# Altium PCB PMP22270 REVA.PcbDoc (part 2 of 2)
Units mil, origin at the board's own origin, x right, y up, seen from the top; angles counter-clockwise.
Board outline 4330.71 x 3937.01 mil, 4 copper layers (Top Layer, Signal Layer 1, Signal Layer 2, Bottom Layer), stack 41.2 mil thick; 92 components, 40 nets, 216 pads, 127 vias.
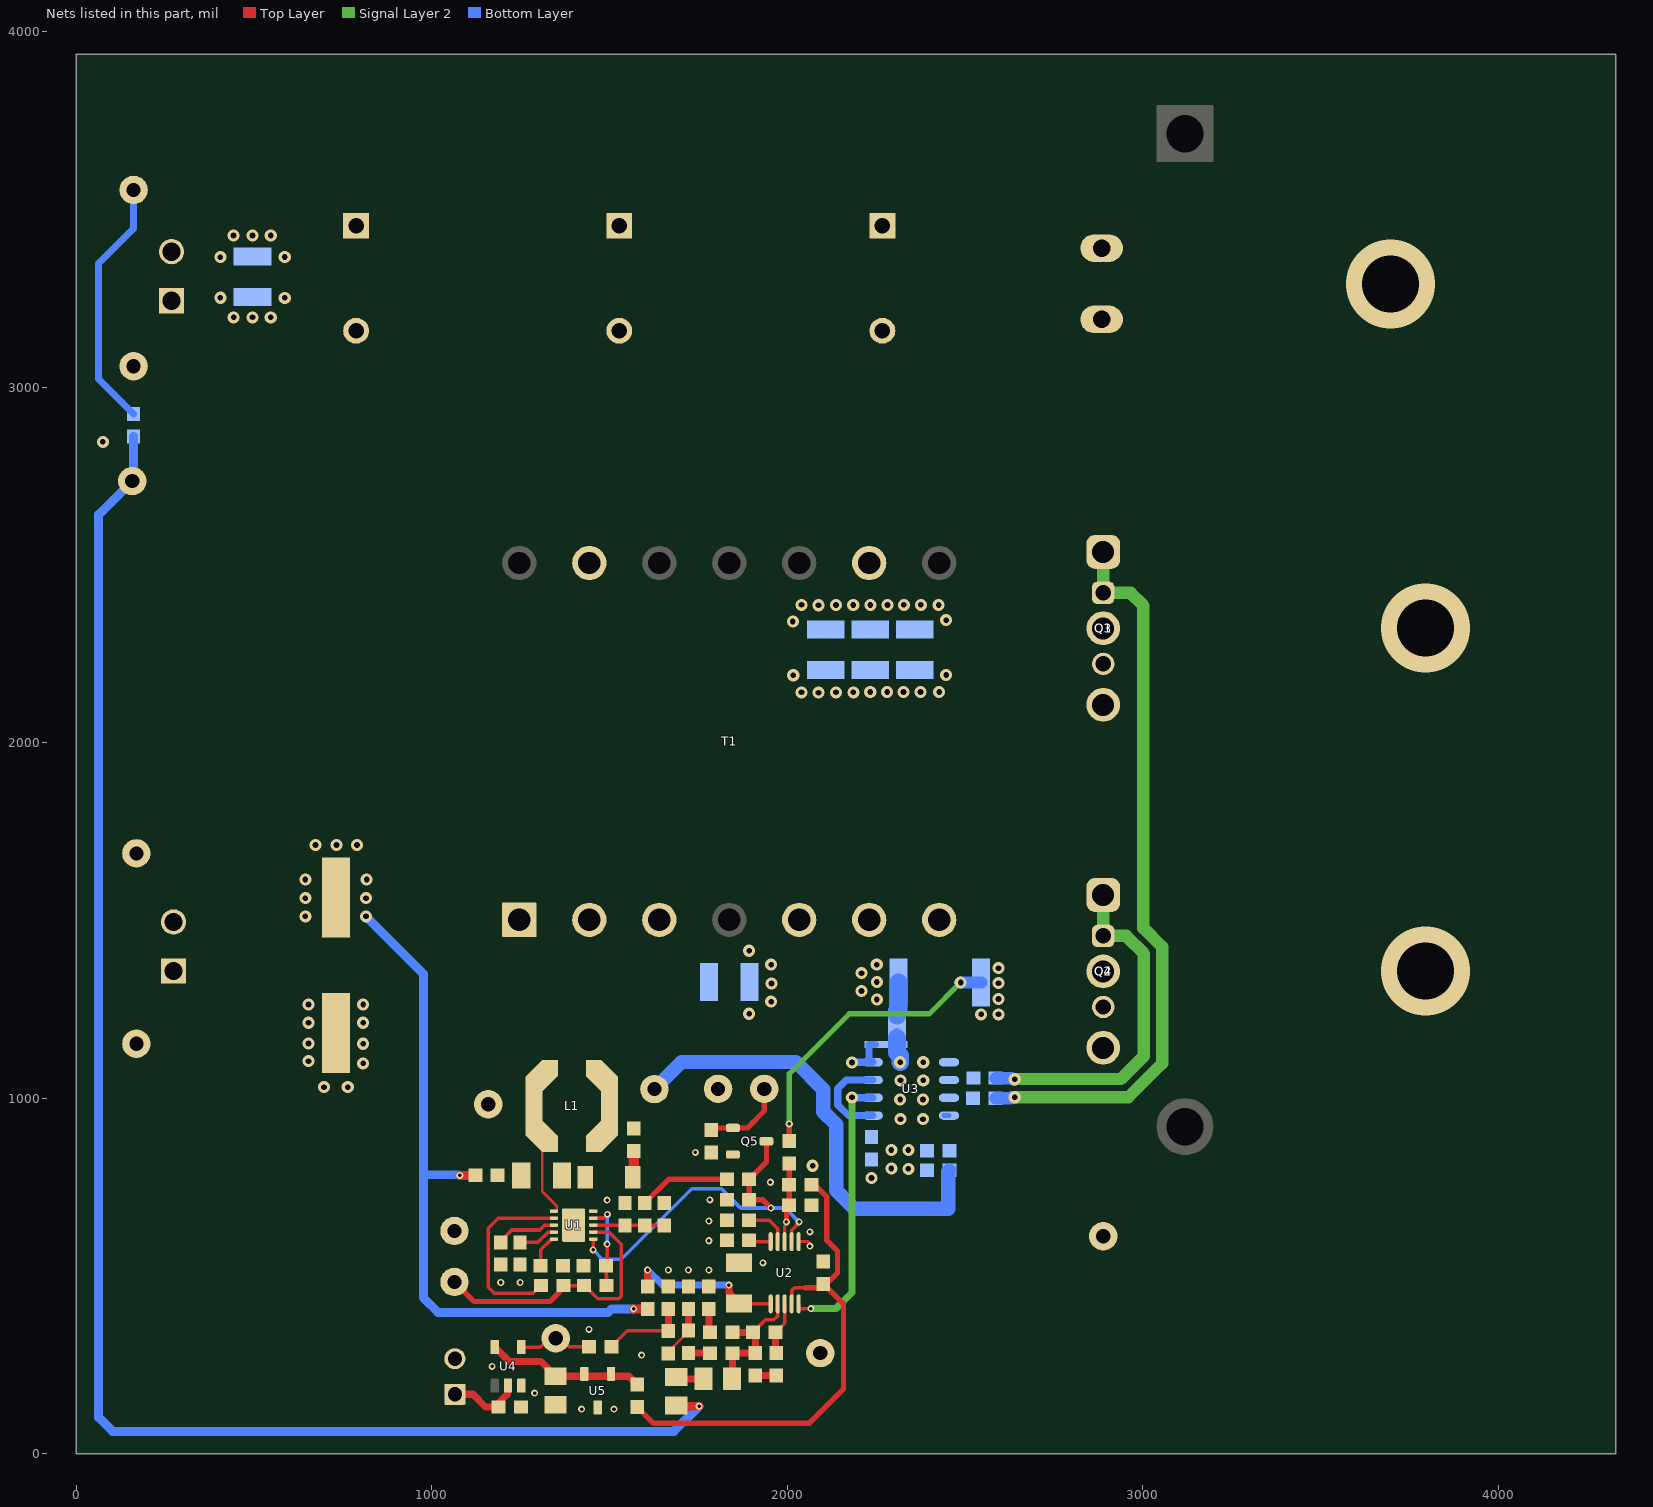
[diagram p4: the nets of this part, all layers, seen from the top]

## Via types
v1: diameter 34, hole 16, Top Layer to Bottom Layer, 86 vias
v2: diameter 20, hole 10, Top Layer to Bottom Layer, 33 vias
v3: diameter 19.68, hole 7.87, Top Layer to Bottom Layer, 4 vias
v4: diameter 250, hole 160, Top Layer to Bottom Layer, 3 vias
v5: diameter 160.24, hole 105.12, Top Layer to Bottom Layer, 1 vias

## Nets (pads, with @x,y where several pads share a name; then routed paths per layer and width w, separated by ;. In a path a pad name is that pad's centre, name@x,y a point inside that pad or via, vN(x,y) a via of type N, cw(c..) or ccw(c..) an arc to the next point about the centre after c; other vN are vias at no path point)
10V: C13.1 C15.1 C18.1 C25.1 L1.2 R3.2 R4.2 R13.2 TP4.1 U3.1 U3.3 U3.8 | length 1827
  Top Layer w10: C25.1@1654.09,704.92 C25.1@1654.09,705.9 ; R13.2@1827.2,769.31 R13.2@1830.06,772.17
  Top Layer w15: R3.2@1599.09,704.92 1666.34,772.17 R13.2@1830.06,772.17
  Bottom Layer w15: U3.8@2440.96,951.47 U3.8@2455.06,951.47
  Bottom Layer w20: U3.1@2240.49,951.47 2172.3,951.47 2142.22,981.56 2142.22,1027.79 2165.91,1051.47 U3.3@2240.49,1051.47
  Bottom Layer w40: TP4.1@1626.53,1025.87 1703.02,1102.36 2024.31,1102.36 2101.56,1025.11 2101.56,962.32 2137.8,926.08 2137.8,740.89 2189.59,689.09 2452.87,689.09 2452.87,794.23 C18.1@2455.96,797.32
Drain: C3.2 C4.2 C6.2 Q1.2 Q2.2 Q3.2 Q4.2 T1.5 T1.6 T1.7 TP7.1
  other v1: 2088,2141 2040,2141.89 2137,2141.89 2186,2142 2233.52,2143 2281,2143 2327,2143 2375,2143 2427.53,2143 2017,2190 2447,2191
  other v4: 3795.28,1358.44 3795.28,2322.83
Gate1: Q1.1 Q3.1 R11.2 | length 2061.8
  Signal Layer 2 w35: v1(2640,1003.12) 2640.12,1003 2959.3,1003 3055,1098.7 3055,1426 3002,1479 3002,2386 2966,2422 Q1.1@2888.83,2422 Q3.1@2888.83,2537
  Bottom Layer w35: R11.2@2586.27,1000.52 2629.52,1000.52 2632.12,1003.12 v1(2640,1003.12)
Gate2: Q2.1 Q4.1 R15.2 | length 983.4
  Signal Layer 2 w35: v1(2640,1053.61) 2640.73,1054.34 2938.81,1054.34 3003,1118.53 3003,1407.3 2953.3,1457 Q2.1@2888.83,1457 Q4.1@2888.83,1572
  Bottom Layer w35: R15.2@2586.5,1057.06 2630.94,1057.06 2634.39,1053.61 v1(2640,1053.61)
GND: C1.2 C2.2 C5.2 C7.2 C8.2 C9.2 C10.2 C11.2 C12.2 C13.2 C14.2 C16.2 C17.2 C21.2 C22.2 C23.2 C24.2 J1.1 J2.1 J3.2 NT1.1 NT2.1 Q5.2 R6.1 R7.1 R8.1 R9.1 R19.1 R21.1 R23.1 R24.1 R25.1 R31.1 T1.13 TP2.1 TP8.1 TP11.1 TP12.1 TP16.1 U1.10 U1.11 U2.6 U3.4 U4.3 U5.3 | length 287.4
  Top Layer w8: U1.10@1447.26,682.79 U1.10@1454.2,682.79 ; U2.6@2032.15,596.91 2058.94,596.91 2063.64,592.21 v2(2063.64,584.31)
  Bottom Layer w20: v1(2182.22,1100.79) 2182.91,1101.47 U3.4@2240.49,1101.47 2229.58,1112.38 2229.58,1151.47 NT2.1@2247.77,1151.47 ; NT1.1@2308.55,1219.79 NT1.1@2308.55,1232.28
  Bottom Layer w50: NT1.1@2308.55,1232.28 2308.55,1246.54 2313.08,1251.07 R25.1@2313.08,1325.79
  other v1: 2237.22,775.79 2071.64,810.42 696.85,1031.5 763.78,1031.5 807.09,1098.43 653.54,1104.64 653.54,1153.97 807.09,1153.54 653.54,1212.6 807.09,1212.6 1892.78,1238 653.54,1263.78 807.09,1263.78 1954.78,1272 2252,1278 2209,1302 1955.78,1323 2252,1327 2209,1352 1954.78,1376 2251.78,1376 1892.78,1415 74.8,2846.46 442.91,3196.85 496.06,3196.85 547.24,3196.85 405.51,3251.97 586.61,3251.53
  other v2: 1421.72,125.77 1512.7,125.77 1289.4,170.77 1169.88,246.08 1590.55,277.85 1442.46,350.22 1194.09,482.01 1248.49,482.01 1665.59,517.03 1722.07,517.03 1779.63,517.03 1931.56,537.33 1779.63,599.31 2063.64,624.31 1779.63,654.94 1493.53,713.46 1782.58,714.31 1952.76,763.87 1741.56,847.82
NetC1_1: C1.1 C2.1 J1.2 R1.2 R12.2 T1.1 T1.2 T1.3 TP1.1 | length 1939.3
  Top Layer w25: v2(1078.74,783.46) 1122.55,783.46 R1.2@1122.59,783.42 ; v2(1567.98,407.6) R12.2@1608.09,407.6
  Bottom Layer w25: v1(814.96,1511.81) 976.38,1350.39 976.38,785.1 ; v2(1078.74,783.46) 1077.1,785.1 976.38,785.1 ; v2(1567.98,407.6) 1506.55,407.6 1496.59,397.64 1018.14,397.64 976.38,439.4 976.38,785.1
  other v1: 644.47,1511.81 644.47,1562.99 814.96,1562.99 644.47,1615.54 817.09,1615.54 673.23,1712.6 732.28,1712.6 789.97,1712.6
NetC3_1: C3.1 C4.1 C6.1 D1.2 T1.9
  other v1: 2016,2341 2447,2345 2088,2387 2040,2388 2137,2387.89 2185.76,2387.89 2233.8,2387.89 2282,2387.89 2328,2388 2376,2388 2426,2387.89
NetC5_1: C5.1 R1.1 R2.2 U1.2 | length 527.8
  Top Layer w10: R2.2@1307.59,473.42 1306.61,473.42 1284.37,451.19 1284.09,451.47 1176.04,451.47 1159.09,468.42 1159.09,634.72 1187.47,663.11 U1.2@1343.97,663.11
NetC7_1: C7.1 U1.4 | length 107.4
  Top Layer w10: C7.1@1248.49,594.92 1298.34,594.92 1327.16,623.74 U1.4@1343.97,623.74
NetC8_1: C8.1 R4.1 | length 74.3
  Top Layer w30: C8.1@1566.01,778.42 1567.98,780.39 R4.1@1567.98,851.93
NetC9_1: C9.1 C10.1 C11.1 C12.1 D1.1 J2.2 R10.1 TP6.1 | length 711.5
  Top Layer w20: TP6.1@161.42,3555.12 TP6.1@161.42,3555.12
  Bottom Layer w20: R10.1@161.42,2925.2 62.99,3023.62 62.99,3348.06 161.42,3446.49 TP6.1@161.42,3555.12
  other v1: 405.51,3366.14 586.61,3366.72 442.54,3426.8 496.06,3426.8 547.24,3426.8
  other v4: 3697,3291
NetC14_1: C14.1 R12.1 U2.1 | length 445.3
  Top Layer w10: C14.1@1864.08,423.16 1865.51,421.72 U2.1@1953.41,421.72
  Top Layer w20: v2(1607.43,517.03) 1607.43,471.25 R12.1@1608.09,470.59 ; v2(1835.73,474.71) 1835.73,453.06 C14.1@1864.08,423.16
  Bottom Layer w20: v2(1607.43,517.03) 1649.75,474.71 v2(1835.73,474.71)
NetC15_2: C15.2 C18.2 NT1.2 NT2.2 U3.5 | length 92.1
  Bottom Layer w15: 2308.55,1169.79 NT1.2@2308.55,1189.79
  Bottom Layer w50: 2308.55,1169.79 2308.55,1128.69 2317.77,1119.47 v1(2317.77,1101.47)
  other v1: 2340.61,801.47 2292.77,802.36 2292.77,854.91 2340.61,854.91 2318.8,941.47 2381.75,941.47 2317.77,996.47 2381.75,996.47 2318.8,1050.53 2382.77,1050.53 2382.77,1101.47
NetC16_1: C16.1 U2.10 | length 62
  Top Layer w10: C16.1@1893.05,600.97 1897.11,596.91 U2.10@1953.41,596.91
NetC19_1: C19.1 R17.2 U2.3 | length 150
  Top Layer w10: C19.1@1967.07,341.72 1992.78,367.43 U2.3@1992.78,421.72
  Top Layer w20: C19.1@1967.07,341.72 1967.07,285.22 R17.2@1969.08,283.21
NetC19_2: C19.2 C20.2 R16.1 R20.2 R30.1 U2.2 | length 373.5
  Top Layer w10: C19.2@1904.08,341.72 1939.08,376.72 1962.05,376.72 1973.09,387.76 U2.2@1973.09,421.72
  Top Layer w20: R16.1@1844.74,210.77 1845.57,211.6 R30.1@1845.57,283.21 ; R20.2@1845.57,341.72 C19.2@1904.08,341.72 1908.92,341.72 1910.34,340.3 C20.2@1910.34,283.21 R30.1@1854.08,283.21
NetC20_1: C20.1 R17.1 | length 58.7
  Top Layer w20: C20.1@1910.34,220.22 R17.1@1969.08,220.22
NetC21_1: C21.1 R18.1 R22.1 U2.8 | length 224.8
  Top Layer w8: U2.8@1992.78,596.91 1992.78,640.3 1997.83,645.36 v2(1997.83,652.23)
  Top Layer w10: C21.1@1997.83,691.45 C21.1@2005.69,699.31
  Top Layer w15: v2(1997.83,652.23) C21.1@1997.83,691.45 ; C21.1@2005.69,699.31 R18.1@2005.69,756.56 R22.1@2005.69,816.32
NetC22_1: C22.1 R26.2 U4.5 U5.1 U5.2 | length 444.4
  Top Layer w20: U4.5@1177.28,300.22 1218.2,259.29 1307.12,259.29 C22.1@1348.09,218.33 1554.67,218.33 R26.2@1578.09,194.9
NetC23_1: C23.1 R27.1 R28.2 | length 240.5
  Top Layer w10: R27.1@1505.45,301.08 1550.14,345.77 R28.2@1665.59,345.77
  Top Layer w20: R28.2@1665.59,345.77 C23.1@1665.59,407.6
NetC24_1: C24.1 R28.1 R29.1 | length 148.2
  Top Layer w8: R28.1@1665.59,282.78 1665.59,287.59 1722.07,344.06 R29.1@1722.07,347.26
  Top Layer w20: R29.1@1722.07,347.26 C24.1@1722.07,407.6
NetC25_2: C25.2 R3.1 R8.2 U1.8 | length 202.1
  Top Layer w10: U1.8@1454.2,643.42 1654.6,643.42 1654.09,642.91 C25.2@1654.09,641.93
NetJ3_1: J3.1 R31.2 U4.2 | length 209.6
  Top Layer w20: J3.1@1065.16,167.54 1116.04,167.54 1151.63,131.95 R31.2@1188.18,131.95 1188.18,143.13 1213,167.95 ; 1213,167.1 1213,167.95 ; U4.2@1214.68,191.95 1213,190.27 1213,167.95
NetL1_1: L1.1 TP3.1 U1.1 | length 236
  Top Layer w8: L1.1@1310.48,893.75 1311,893.23 1311,738.18 1351.89,697.3 1351.89,682.79 U1.1@1343.97,682.79
NetQ5_1: Q5.1 R23.2 TP10.1 | length 233.5
  Top Layer w15: R23.2@1786.56,910.81 1792.46,916.72 Q5.1@1847.07,916.72 1888.09,916.72 1935.51,964.14 TP10.1@1935.51,1026.6
NetR2_1: R2.1 R5.2 TP5.1 U1.7 | length 771.7
  Top Layer w10: R2.1@1370.58,473.42 R5.2@1428.61,473.42 1429.6,473.42 1466.95,436.07 1525.28,436.07 1532.87,443.66 1532.87,589.64 1498.77,623.74 U1.7@1454.2,623.74
  Top Layer w15: TP5.1@1064.09,483.46 1119.09,428.46 1332.66,428.46 1360.72,456.51 1360.72,463.56 R2.1@1370.58,473.42
NetR5_1: R5.1 R6.2 U1.9 | length 245.6
  Top Layer w10: U1.9@1454.2,663.11 1471.01,663.11 1471.33,663.42 1484.09,663.42 v2(1494.09,673.42) ; R5.1@1491.61,473.42 R6.2@1490.58,528.98 1493.53,531.93 v2(1493.53,589.88)
  Bottom Layer w10: v2(1493.53,589.88) 1494.09,590.43 v2(1494.09,673.42)
NetR7_2: R7.2 U1.3 | length 172.1
  Top Layer w10: R7.2@1194.09,594.92 1194.09,598.58 1225.11,629.61 1303.61,629.61 1317.43,643.42 U1.3@1343.97,643.42
NetR9_2: R9.2 U1.5 | length 94.7
  Top Layer w10: R9.2@1306.57,528.98 1306.57,573.74 1336.88,604.05 U1.5@1343.97,604.05
NetR10_2: R10.2 R14.2 TP9.1 | length 4599.9
  Top Layer w25: R14.2@1688.09,135.77 1690,133.86 v2(1751.97,133.86)
  Bottom Layer w25: R10.2@161.42,2862.2 161.42,2740.16 TP9.1@157.48,2736.22 62.99,2641.73 62.99,102.36 102.36,62.99 1681.1,62.99 v2(1751.97,133.86)
NetR11_1: R11.1 R15.1 U3.6 U3.7
NetR14_1: R14.1 R16.2 | length 78.7
  Top Layer w20: R14.1@1688.09,215.77 1693.09,210.77 R16.2@1764.74,210.77
NetR19_2: R19.2 U2.9 | length 126.1
  Top Layer w10: R19.2@1893.05,656.83 1949.47,656.83 1973.09,633.21 U2.9@1973.09,596.91
NetR20_1: R20.1 R24.2 | length 67.1
  Top Layer w15: R20.1@1779.63,344.67 R20.1@1782.58,341.72
  Top Layer w20: R20.1@1779.63,344.67 R24.2@1779.63,407.6
NetR27_2: R27.2 TP14.1 U4.4 | length 210.7
  Top Layer w10: U4.4@1252.08,300.22 1305.1,300.22 1330.03,325.14 TP14.1@1348.96,325.14 1363.17,325.14 1387.22,301.08 R27.2@1442.46,301.08
NetR29_2: R29.2 R30.2 | length 61
  Top Layer w20: R29.2@1722.07,284.27 1723.13,283.21 R30.2@1782.58,283.21
NetU2_5: U2.5 U3.2 | length 801.8
  Top Layer w10: U2.5@2032.15,421.72 2032.15,406.47 2033.95,408.28 v2(2066.56,408.28)
  Signal Layer 2 w20: v2(2066.56,408.28) 2136.7,408.28 2182.22,453.8 v1(2182.22,1002.79)
  Bottom Layer w20: v1@2173.73,1001.47 2175.04,1002.79 v1(2182.22,1002.79) 2183.54,1001.47 U3.2@2240.49,1001.47
PG: Q5.3 R13.1 R21.2 U1.6 U2.7 | length 1060.5
  Top Layer w10: v2(1454.09,573.74) 1454.2,573.86 U1.6@1454.2,604.05 ; U2.7@2012.46,596.91 2012.46,629.31 2033.29,650.15 v2(2033.29,652.23)
  Top Layer w15: Q5.3@1941.56,879.31 1941.56,820.68 R13.1@1893.05,772.17 R21.2@1893.05,714.31 1931.41,714.31 v2(1954.27,691.45)
  Bottom Layer w10: v2(1454.09,573.74) 1480.15,547.68 1533.6,547.68 1731.19,745.26 1814.96,745.26 1868.77,691.45 v2(1954.27,691.45) 1994.07,691.45 v2(2033.29,652.23)
Source: Q1.3 Q2.3 Q3.3 Q4.3 R22.2 R25.2 | length 835.6
  Top Layer w15: R22.2@2005.69,879.31 v2(2005.69,928.05)
  Signal Layer 2 w15: v2(2005.69,928.05) 2005.69,1068.86 2174.83,1238 2400.01,1238 v1(2487.8,1325.79)
  Bottom Layer w35: v1(2487.8,1325.79) R25.2@2545.36,1325.79
  other v1: 2545.36,1236.22 2594.49,1236.22 2594.49,1279.53 2594.49,1324 2594.49,1366.14
VCC: C17.1 R18.2 R26.1 U2.4 | length 1429.5
  Top Layer w10: U2.4@2012.46,421.72 2012.46,459.31 2020.59,467.45 2050.46,467.45
  Top Layer w15: R26.1@1578.09,131.91 1624.23,85.77 2061.56,85.77 2158.09,182.3 2158.09,421.28 C17.1@2101.56,477.82 ; 2050.46,467.45 2091.18,467.45 C17.1@2101.56,477.82 ; R18.2@2069.43,757.31 R18.2@2068.68,756.56 2077.97,756.56 2111.56,722.98 2111.56,600.34 2141.56,570.34 2141.56,509 2120.24,487.68 2111.42,487.68 C17.1@2101.56,477.82
pads on no net: MP1.1 MP1.2 T1.4 T1.8 T1.10 T1.11 T1.12 T1.14 U4.1
copper on no net:
  other v3: 1399.09,606.02 1376.45,643.42 1421.72,643.42 1399.09,680.83
  other v5: 3118.95,2887.05

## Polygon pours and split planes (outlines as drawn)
GND on Bottom Layer "BOTTOM_LAYER_GND_P116" (solid, remove dead copper, pour order 116): 0,3303.15 3.94,3307.09 2273.62,3307.09 2325.47,3255.24 2325.47,2955.39 1969.78,2599.7 1969.78,2130.22 2008,2092 2435.56,2092 2488.19,2039.37 2486.32,2037.5 2486.32,1286.24 2473.93,1273.85 2183.54,1273.85 2183.54,1167.56 1895.3,879.31 1.36,879.31 0,877.95
Drain on Bottom Layer "BOTTOM_LAYER_DRAIN_P114" (solid, remove dead copper, pour order 114): 2021.78,2234 1995.78,2208 1995.78,2144.22 2019,2121 2443,2121 2476,2154 2476,2202.88 2444.88,2234
NetC1_1 on Bottom Layer "BOTTOM_LAYER_NETC1_1_P108" (solid, remove dead copper, pour order 108): 92.03,1440.94 92.03,1440.95 722.28,1440.95 722.28,1437.01 939.5,1219.79 1754.71,1219.79 1807.3,1272.38 1807.3,1945.94 1686.31,2066.93 92.03,2066.93
NetC3_1 on Bottom Layer "BOTTOM_LAYER_NETC3_1_P104" (solid, remove dead copper, pour order 104): 1996.06,2322.83 2027.56,2291.34 2425.45,2291.34 2988.19,2854.08 2988.19,3306.89 2987.99,3307.09 2393.7,3307.09 2346.46,3259.84 2346.46,2937.01 2074.8,2665.35 2074.8,2513.25 2060.18,2513.25 1996.06,2449.14
GND on Bottom Layer "BOTTOM_LAYER_GND_P084" (solid, remove dead copper, pour order 84): 0,0 0,1405.51 708.66,1405.51 925.2,1188.98 1761.71,1188.98 1832.78,1260.04 1832.78,1409.33 1848.64,1425.2 2465.55,1425.2 2488.19,1402.56 2488.19,1170.82 2562.99,1096.01 2562.99,0
NetC15_2 on Bottom Layer "BOTTOM_LAYER_NETC15_2_P074" (solid, remove dead copper, pour order 74): 2413.3,1066.84 2432.93,1086.47 2477.22,1086.47 2482.77,1092.03 2482.77,1174.71 2452.76,1204.72 2283.86,1204.72 2283.46,926.08 2271.65,914.27 2271.65,773.35 2285.61,759.39 2402.28,759.39 2413.39,770.5
10V on Bottom Layer "BOTTOM_LAYER_10V_P072" (solid, remove dead copper, pour order 72): 2261.74,958.95 2260.78,957.99 2260.78,872.12 2209.19,872.12 2196.85,859.79 2196.85,759.84 2212.6,744.09 2413.3,744.09 2433.35,764.15 2605.93,764.15 2606.3,763.78 2562.99,720.47 2200.79,720.47 2169.29,751.97 2169.29,964.14 2169.72,964.57 2240.22,964.57 2245.83,958.95
10V on Bottom Layer "BOTTOM_LAYER_10V_P070" (solid, remove dead copper, pour order 70): 2433.65,958.95 2433.65,834.81 2433.07,834.23 2433.07,763.87 2448.91,748.03 2590.55,748.03 2606.3,763.78 2606.3,943.52 2605.98,943.52 2590.55,958.95
NetC9_1 on Bottom Layer "BOTTOM_LAYER_NETC9_1_P058" (solid, remove dead copper, pour order 58): 4330.71,2834.65 3027.56,2834.65 3027.56,3322.83 3011.81,3338.58 0,3338.58 0,3937.01 4330.71,3937.01
NetR11_1 on Bottom Layer "BOTTOM_LAYER_NETR11_1_P044" (solid, remove dead copper, pour order 44): 2437.01,1063.09 2486.32,1063.09 2497.05,1073.82 2543.31,1073.82 2543.31,981.82 2494.56,981.82 2487.21,989.17 2445.95,989.17 2437.01,998.11
Source on Bottom Layer "BOTTOM_LAYER_SOURCE_P040" (solid, remove dead copper, pour order 40): 3948.82,2992.13
Source on Bottom Layer "BOTTOM_LAYER_SOURCE_P038" (solid, remove dead copper, pour order 38): 2516.78,2328 2559.78,2371 2987.99,2799.21 4330.71,2799.21 4330.71,0 2755.91,0 2653.54,102.36 2653.54,1153.76 2619.31,1188 2529.7,1188 2516.78,1200.93
NetC15_2 on Bottom Layer "BOTTOM_LAYER_NETC15_2_P012" (solid, remove dead copper, pour order 12): 2446.27,1023.82
no net on Bottom Layer "BOTTOM_LAYER_NONET_P014" (solid, remove dead copper, pour order 14): 1880.26,1084.72
GND on Top Layer "TOP_LAYER_GND_P112" (solid, remove dead copper, pour order 112): -3.94,1151.47 0.36,1155.77 0.36,3306.72 2273.98,3306.72 2325.47,3255.24 2325.47,2955.39 1969.78,2599.7 1969.78,2320.57 1939.85,2290.65 1939.85,1447.7 1982.51,1405.04 1982.51,1149.32
NetC1_1 on Top Layer "TOP_LAYER_NETC1_1_P110" (solid, remove dead copper, pour order 110): 651.71,1739.83 617.23,1705.36 617.23,1487.21 652.6,1451.84 810.11,1451.84 844.32,1486.05 844.32,1702.89 807.37,1739.83
NetC3_1 on Top Layer "TOP_LAYER_NETC3_1_P094" (solid, remove dead copper, pour order 94): 1996.06,2322.83 2027.56,2291.34 2425.01,2291.34 2425.01,2291.74 2987.99,2854.72 2987.99,3307.09 2393.7,3307.09 2346.46,3259.84 2346.46,2937.01 2074.8,2665.35 2074.8,2527.88 1996.06,2449.14
GND on Top Layer "TOP_LAYER_GND_P082" (solid, remove dead copper, pour order 82): 0,3.94 0,1405.51 708.66,1405.51 925.2,1188.98 1744.09,1188.98 1795.28,1240.16 1795.28,1413.9 1806.57,1425.2 2465.55,1425.2 2488.19,1402.56 2488.19,1170.82 2562.99,1096.01 2562.99,0
NetC9_1 on Top Layer "TOP_LAYER_NETC9_1_P056" (solid, remove dead copper, pour order 56): 4330.71,2834.65 3027.56,2834.65 3027.56,3322.83 3011.81,3338.58 0,3338.58 0,3937.01 4330.71,3937.01
Drain on Top Layer "TOP_LAYER_DRAIN_P036" (solid, remove dead copper, pour order 36): 1969.78,1472 1969.78,2182 2021.78,2234 2422.78,2234 2559.78,2371 2987.99,2799.21 4330.71,2799.21 4330.71,0 2755.91,0 2657.48,98.43 2657.48,1342.22 2554.81,1444.88 1996.89,1444.88
10V on Top Layer "TOP_LAYER_10V_P006" (solid, remove dead copper, pour order 6): 1434.09,848.42 1517.79,848.42 1534.09,864.72 1534.09,883.07 1539.44,888.42 1595.98,888.42 1604.09,880.32 1604.09,711.22 1613.45,701.85 1672.79,701.85 1672.79,828.09 1672.43,828.44 1672.79,828.8 1672.79,1043.07 1607.43,1108.42 1432.16,1108.42
NetL1_1 on Top Layer "TOP_LAYER_NETL1_1_P002" (solid, remove dead copper, pour order 2): 1360.74,669 1360.74,691.77 1328.77,723.74 1328.77,833.11 1354.09,858.42 1354.09,1108.42 1224.09,1108.42 1119.64,1003.98 1119.64,956.79 1238,838.42 1280.35,838.42 1287.86,830.26 1287.86,706.22 1325.08,669
NetC5_1 on Top Layer "TOP_LAYER_NETC5_1_P000" (solid, remove dead copper, pour order 0): 1279.09,818.86 1277.04,816.81 1277.04,704.72 1313.34,668.42 1356.33,668.42 1356.33,656.97 1354.09,654.72 1306.57,654.72 1295.27,643.42 1173.89,643.42 1164.09,653.23 1164.09,806.77 1175.74,818.42
NetC14_1 on Top Layer "TOP_LAYER_NETC14_1_P008" (solid, remove dead copper, pour order 8): 1975.84,443.67 1970.66,448.85 1834.78,448.85 1834.78,399.83 1975.84,399.83
NetC3_1 on Signal Layer 1 "SIGNAL_LAYER_1_NETC3_1_P092" (solid, remove dead copper, pour order 92): 2027.56,2291.34 1996.06,2322.83 1996.06,2484.31 2074.8,2563.05 2074.8,2665.35 2346.46,2937.01 2346.46,3259.84 2393.7,3307.09 2987.99,3307.09 2987.99,2854.72 2425.01,2291.34
Drain on Signal Layer 1 "SIGNAL_LAYER_1_DRAIN_P090" (solid, remove dead copper, pour order 90): 2021.78,2234 1995.78,2208 1995.78,2165.64 1996.56,2143.44 2019,2121 2443,2121 2476,2154 2476,2202.88 2444.88,2234
GND on Signal Layer 1 "SIGNAL_LAYER_1_GND_P088" (solid, remove dead copper, pour order 88): 0,3307.09 0.36,3306.72 2273.98,3306.72 2322.03,3258.68 2322.03,2951.95 1969.78,2599.7 1969.78,2130.22 2008,2092 2435.56,2092 2488.19,2039.37 2488.19,1391.66 2268.62,1172.08 1.15,1172.08 0,1173.23
GND on Signal Layer 1 "SIGNAL_LAYER_1_GND_P076" (solid, remove dead copper, pour order 76): -7.87,1425.2 2465.8,1425.2 2465.8,1424.95 2488.19,1402.56 2488.19,1170.82 2562.99,1096.01 2562.99,3.94 2559.06,0 0,0
NetC9_1 on Signal Layer 1 "SIGNAL_LAYER_1_NETC9_1_P060" (solid, remove dead copper, pour order 60): 4330.71,3937.01 4330.71,2834.65 3027.56,2834.65 3027.56,3322.83 3011.81,3338.58 0,3338.58 0,3937.01
Source on Signal Layer 1 "SIGNAL_LAYER_1_SOURCE_P042" (solid, remove dead copper, pour order 42): 2755.91,0 2653.54,102.36 2653.54,1153.76 2619.31,1188 2529.7,1188 2516.78,1200.93 2516.78,2328 2559.78,2371 2987.99,2799.21 4330.71,2799.21 4330.71,0
Source on Signal Layer 2 "SIGNAL_LAYER_2_SOURCE_P118" (solid, remove dead copper, pour order 118): 2516.78,2328 2987.99,2799.21 4330.71,2799.21 4330.71,1 4329.71,0 2757,0 2757,4.54 2653.54,108 2653.54,1156.47 2622.02,1188 2529.7,1188 2516.78,1200.93
GND on Signal Layer 2 "SIGNAL_LAYER_2_GND_P100" (solid, remove dead copper, pour order 100): 2488.19,1391.73 2267.93,1171.47 1.75,1171.47 0,1173.23 0,3307.09 2273.62,3307.09 2322.03,3258.68 2322.03,2951.95 1969.78,2599.7 1969.78,2130.22 2009,2091 2436.56,2091 2488.19,2039.37
NetC3_1 on Signal Layer 2 "SIGNAL_LAYER_2_NETC3_1_P098" (solid, remove dead copper, pour order 98): 1996.06,2322.83 2027.56,2291.34 2413.04,2291.34 2417.32,2287.05 2984.79,2854.52 2988.19,2854.52 2988.19,3306.89 2987.99,3307.09 2393.7,3307.09 2346.46,3259.84 2346.46,2937.01 2074.8,2665.35 2074.8,2527.88 1996.06,2449.14
Drain on Signal Layer 2 "SIGNAL_LAYER_2_DRAIN_P096" (solid, remove dead copper, pour order 96): 2021.78,2234 1995.78,2208 1995.78,2144.22 2019,2121 2443,2121 2476,2154 2476,2204.47 2446.47,2234
GND on Signal Layer 2 "SIGNAL_LAYER_2_GND_P086" (solid, remove dead copper, pour order 86): 0,0 0,1425.2 2465.55,1425.2 2488.19,1402.56 2488.19,1170.82 2562.99,1096.01 2562.99,0
NetC15_2 on Signal Layer 2 "SIGNAL_LAYER_2_NETC15_2_P068" (solid, remove dead copper, pour order 68): 2283.8,1204.72 2283.46,1204.39 2283.46,926.08 2271.65,914.27 2271.65,764.15 2287.77,748.03 2590.55,748.03 2606.3,763.78 2606.3,1141.91 2586.73,1161.47 2497.05,1161.47 2458.91,1199.61 2458.91,1204.72
NetC9_1 on Signal Layer 2 "SIGNAL_LAYER_2_NETC9_1_P062" (solid, remove dead copper, pour order 62): 4330.71,3937.01 4330.71,2834.65 3027.56,2834.65 3027.56,3322.83 3011.81,3338.58 0,3338.58 0,3937.01

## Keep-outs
Keep-Out Layer:
  text ".Layer_Name" at 577,-858.49 h60

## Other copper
Top Layer:
  region net GND: 1366,552 1366.6,552.6 1366.6,744 1496.13,744 1499.09,741.04 1469,710.96 1469,678.42 1431.57,678.42 1431.57,659.2 1431.37,659 1431.57,658.8 1431.57,553
  text ".Layer_Name" at 577,-858.49 h60
Signal Layer 1:
  region net GND: 1374.13,578.07 1408.54,578.07 1454.2,623.74 1454.2,703.74 1425.66,732.28 1354.09,732.28 1354.09,696.52 1335.99,678.42 1336.88,677.54 1336.88,604.05
  pour cut-out: 2890,1425.75 2853.75,1425.75 2821.9,1393.9 2821.9,1324.32 2856.22,1290 2921.99,1290 2953.79,1321.8 2953.79,1393.01 2918.8,1428 2900,1428
  pour cut-out: 2890,1425.75 2853.75,1425.75 2821.9,1393.9 2821.9,1324.32 2856.22,1290 2921.99,1290 2953.79,1321.8 2953.79,1393.01 2918.8,1428 2900,1428
  pour cut-out: 2890,2390.75 2853.75,2390.75 2821.9,2358.9 2821.9,2289.32 2856.22,2255 2921.99,2255 2953.79,2286.8 2953.79,2358.01 2918.8,2393 2900,2393
  pour cut-out: 2850.58,2403
Signal Layer 2:
  region net GND: 1348.58,729.29 1456.69,729.29 1454.2,726.8 1454.2,616.78 1398.06,560.64 1391.63,567.07 1348.09,567.07
  pour cut-out: 2887,1420 2886.32,1419.32 2851.15,1419.32 2821,1389 2821,1331.93 2862.93,1290 2914.63,1290 2953.79,1329.16 2953.79,1388.21 2921,1421
  pour cut-out: 2887,2385 2886.32,2384.32 2851.15,2384.32 2821,2354 2821,2296.93 2862.93,2255 2914.63,2255 2953.79,2294.16 2953.79,2353.21 2921,2386
  pour cut-out: 3153.54,778.42
Bottom Layer:
  region net GND: 1348.96,722.98 1452.76,722.98 1452.76,615.34 1398.06,560.64 1398.06,557.52 1355.13,557.52 1348.96,563.69
  pour cut-out: 2887,2385 2886.32,2384.32 2847.32,2384.32 2821.9,2358.9 2821.9,2289.32 2856.22,2255 2921.99,2255 2953.79,2286.8 2953.79,2358.01 2926.8,2385
  pour cut-out: 2891,1419 2847,1419 2821.9,1393.9 2821.9,1324.32 2856.22,1290 2921.99,1290 2953.79,1321.8 2953.79,1394 2927.92,1419.87 2894.7,1419.87 2894,1419.17
  text ".Layer_Name" at 577,-858.49 h60

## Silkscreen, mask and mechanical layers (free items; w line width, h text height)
Top Overlay:
  lines w9: 1226.26,378.07 1226.26,377.77 1278.89,325.14 1293.48,325.14 ; 2007,363 2145.09,363 2162,363 2213,312 ; 2090.11,418.03 2167.41,418.03 2168,417.44
  text "VOUT" at 52,3465 h40 r270
  text "GND" at 53,3267 h40 r270
  text "VIN" at 51,1559 h40 r270
  text "GND" at 52,1397 h40 r270
  text "'.PRJ_Number'.PCB_Rev" at 3286,266.27 h108.27
  text "GND" at 859,247 h40
  text "PWM" at 859,143.13 h40
  text ".Layer_Name" at 577,-858.49 h60
Bottom Overlay:
  text ".Layer_Name" at 577,-858.49 h60
Top Paste:
  text ".Layer_Name" at 577,-858.49 h60
Bottom Paste:
  text ".Layer_Name" at 577,-858.49 h60
Top Solder:
  text ".Layer_Name" at 577,-858.49 h60
  text ".Layer_Name" at 577,-858.49 h60
Bottom Solder:
  text ".Layer_Name" at 577,-858.49 h60
Drill Guide:
  text ".Layer_Name" at 577,-858.49 h60
M1 Board Outline:
  lines w9: 0,0 0,3937.01 4330.71,3937.01 4330.71,0 0,0
  lines w10: 0,0 0,3937.01 4330.71,3937.01 4330.71,0 0,0
  text ".Layer_Name" at 577,-858.49 h60
M2 Board Dimensions:
  rectangle: 0,-275 125,-150
  rectangle: 125,-400 500,-275
  lines w7: 0,-275 1000,-275 ; 125,-400 125,-150 ; 250,-400 250,-150 ; 500,-400 500,-150 ; 750,-400 750,-150 ; 0,-400 1000,-400 1000,-150 0,-150 0,-400
  text ".Layer_Name" at 577,-858.49 h60
M3 3D STEP Top:
  text ".Layer_Name" at 577,-858.49 h60
M4 3D STEP Bottom:
  text ".Layer_Name" at 577,-858.49 h60
M5 Assembly Top:
  lines w10: -292,-930.17 6308,-930.17 ; -292,-726.83 6310,-726.83 ; -292,-523.5 -292,-1133.5 3713,-1133.5 6310,-1133.5 6310,-523.5 -291.5,-523.5 -291.5,-1133.5 1284,-1133.5 ; 2173,-1133.5 2173,-523.5 ; 3440,-726.83 3440,-523.5 ; 4280,-726.83 4280,-523.5 ; 4902,-1140 4902,-937.17
  text "COMPONENTS MARKED 'DNP' SHOULD NOT BE POPULATED." at 1153.5,-318.5 h60
  text "ASSEMBLY VARIANT:" at 1153,-434 h60
  text ".VariantName" at 2189,-434 h60
  text "PCB VIEWED FROM TOP SIDE" at -228.5,-655.67 h60
  text "BOARD #:" at 2248,-655.67 h60
  text ".PRJ_Number" at 2793.5,-655.67 h60
  text "REV:" at 3638,-655.67 h60
  text ".PCB_Rev" at 3929.5,-655.67 h60
  text "SVN REV:" at 4476,-655.67 h60
  text ".VersionControl_RevNumber" at 4982,-655.67 h60
  text "TID #:" at 2248,-859 h60
  text ".TID" at 2793.5,-859 h60
  text "PLOT NAME =" at -228.5,-1064.34 h60
  text ".plot_File_Name" at 577,-1064.34 h60
  text "GENERATED    :" at 2250,-1064.34 h60
  text ".Print_Date" at 3119.5,-1064.34 h60
  text ".Print_Time" at 3848.5,-1064.34 h60
  text "TEXAS INSTRUMENTS" at 5113,-1064.34 h60
M6 Assembly Bottom:
  lines w10: -292.5,-727.33 6309.5,-727.33 ; -290.5,-930.67 6309.5,-930.67 ; 1115.5,-1140.5 1115.5,-937.67 ; 1737.5,-727.33 1737.5,-524 ; 2577.5,-727.33 2577.5,-524 ; 3844.5,-1134 3844.5,-524 ; 4733.5,-1134 6309,-1134 6309,-524 -292.5,-524 -292.5,-1134 2304.5,-1134 6309.5,-1134 6309.5,-524
  text "COMPONENTS MARKED 'DNP' SHOULD NOT BE POPULATED." at 6102,-318 h60
  text ".VariantName" at 5058,-434 h60
  text "ASSEMBLY VARIANT:" at 6097,-434 h60
  text ".VersionControl_RevNumber" at 1035.5,-656.17 h60
  text "SVN REV:" at 1541.5,-656.17 h60
  text ".PCB_Rev" at 2088,-656.17 h60
  text "REV:" at 2379.5,-656.17 h60
  text ".PRJ_Number" at 3224,-656.17 h60
  text "BOARD #:" at 3769.5,-656.17 h60
  text "PCB VIEWED FROM BOTTOM SIDE" at 6246,-656.17 h60
  text ".TID" at 3224,-859.5 h60
  text "TID #:" at 3769.5,-859.5 h60
  text "TEXAS INSTRUMENTS" at 904.5,-1064.84 h60
  text ".Print_Time" at 2169,-1064.84 h60
  text ".Print_Date" at 2898,-1064.84 h60
  text "GENERATED    :" at 3767.5,-1064.84 h60
  text ".plot_File_Name" at 5440.5,-1064.84 h60
  text "PLOT NAME =" at 6246,-1064.84 h60
M9 Title Sheet:
  drawing of 57 lines, arcs and shapes, not listed
  text "1" at 739.84,8036.5 h70
  text "2" at 3235.5,8036.5 h70
  text "3" at 5724.84,8036.5 h70
  text "4" at 8231.51,8036.5 h70
  text "5" at 10730.5,8036.5 h70
  text "6" at 13235.5,8036.5 h70
  text "A" at -416.5,6893.5 h70
  text "A" at 14383.5,6893.5 h70
  text "B" at -416.5,4513.5 h70
  text "B" at 14383.5,4513.5 h70
  text "C" at -416.5,2138.5 h70
  text "C" at 14383.5,2138.5 h70
  text "PROJECT TITLE:" at 11343.5,277.5 h45
  text ".PRJ_Title" at 11393.5,144.17 h70
  text "DESIGNED FOR:" at 11343.5,-23.5 h45
  text ".PRJ_Customer" at 11393.5,-163.5 h70
  text "D" at -416.5,-231.5 h70
  text "D" at 14383.5,-231.5 h70
  text "FILE NAME:" at 11343.5,-323.5 h45
  text ".PCB_File_Name_No_Path" at 11393.5,-443.5 h70
  text "Texas Instruments (TI) and/or its licensors do not warrant the accuracy or completeness of this specification" at 6374,-605.34 h45
  text "ENGINEER:" at 11343.5,-613.5 h45
  text "LAYOUT BY:" at 12848.5,-613.5 h45
  text "or any information contained therein. TI and/or its licensors do not warrant that this design will meet" at 6329.01,-718 h45
  text ".PRJ_Engineer" at 11393.5,-768.49 h70
  text ".PCB_Layout" at 12899,-768.49 h70
  text "the specifications, will be suitable for your application or fit for any particular purpose, or will operate in" at 6329.01,-830.67 h45
  text ".Layer_Name" at 577,-858.49 h60
  text "ALTIUM DESIGNER VERSION:" at 12848.5,-923.5 h45
  text "an implementation. TI and/or its licensors do not warrant that the design is production worthy. You should" at 6329.01,-943.33 h45
  text "completely validate and test your design implementation to confirm the system functionality for your application." at 6374,-1056 h45
  text ".print_Scale" at 11393.5,-1056.83 h70
  text ".Application_BuildNumber" at 12899,-1056.83 h70
  text "1" at 739.84,-1263.5 h70
  text "2" at 3235.5,-1263.5 h70
  text "3" at 5724.84,-1263.5 h70
  text "4" at 8231.51,-1263.5 h70
  text "5" at 10730.5,-1263.5 h70
  text "6" at 13235.5,-1263.5 h70
M10 Fab Notes:
  drawing of 189 lines, arcs and shapes, not listed
  text "DESIGN INFORMATION" at 12382.02,6356.17 h60
  text "MIN. TRACK WIDTH:" at 11737.46,6224.05 h60
  text "8" at 12833.7,6224.05 h60
  text "MIL" at 12988.46,6224.05 h60
  text "MIN. CLEARANCE:" at 11737.46,6099.92 h60
  text "0.2" at 12773.7,6099.93 h60
  text "mm" at 12988.46,6099.92 h60
  text "MIN. VIA PAD SIZE:" at 11737.46,5975.8 h60
  text "24" at 12803.71,5975.8 h60
  text "MIL" at 12988.46,5975.8 h60
  text "0.05mm (2MIL)" at 12432.46,5845.9 h60
  text "MINIMUM ANNULAR RING" at 11408.23,5837.67 h60
  text "EXTERNAL" at 13140.46,5837.67 h60
  text "PER" at 11608.23,5727.55 h60
  text "IPC-D-275 CLASS 2 LEVEL C" at 11828.23,5727.54 h60
  text "MIL, HOLES" at 13316.46,5627.07 h60
  text "+/-" at 12924,5618.48 h60
  text "+/-" at 13778,5618.48 h60
  text "REGISTRATION TOLERANCES:" at 11408.23,5617.42 h60
  text "METAL" at 12608,5617.42 h60
  text "5" at 13184.2,5617.42 h60
  text "3" at 14017.2,5617.42 h60
  text "MIL" at 14133.46,5617.42 h60
  text "HOLE SIZE TOLERANCE (UNLESS OTHERWISE SPECIFIED):" at 11408.23,5519.1 h60
  text "+/-" at 13778,5516.23 h60
  text "3" at 14017.2,5515.17 h60
  text "MIL" at 14133.46,5515.17 h60
  text "MATERIAL:" at 11333.46,5377.52 h60
  text "FR-4 High Tg" at 12319.9,5249 h60
  text "X" at 12175.46,5241.01 h60
  text "FR-408" at 11754.46,5236.49 h60
  text "OTHER" at 13242.46,5236.49 h60
  text "62 MIL (1.6mm) +/-10%" at 12074.56,5093.46 h60
  text "X" at 11954.46,5091.01 h60
  text "THICKNESS:" at 11408.23,5085.24 h60
  text "OTHER" at 13359.46,5085.24 h60
  text "TOLERANCE:" at 11408.23,4946.92 h60
  text "X" at 12256.46,4946.92 h60
  text "ANSI IPC-6012 TYPE 3 CLASS 2" at 12434.48,4946.92 h60
  text "OTHER +/-" at 12434.46,4802.73 h60
  text "BOW & TWIST:" at 11408.23,4657.54 h60
  text "X" at 12256.46,4657.54 h60
  text "ANSI IPC-6012 TYPE 3 CLASS 2" at 12434.48,4657.54 h60
  text "OTHER +/-" at 12434.46,4510.85 h60
  text "DRILLING:" at 11333.46,4380.23 h60
  text "NC_DRILL FILES" at 13094.46,4275.04 h60
  text "REFERENCE:" at 11408.23,4271.1 h60
  text "X" at 12065.46,4271.01 h60
  text "AS SHOWN" at 12243.46,4271.1 h60
  text "X" at 12966.46,4271.1 h60
  text "OTHER" at 13392.46,4128.85 h60
  text "PTH COPPER THICKNESS:" at 11407.91,4125.32 h60
  text "X" at 12547.14,4125.32 h60
  text "20-30 um" at 12675.14,4125.32 h60
  text "BOARD FINISH:" at 11333.46,3977.73 h60
  text "SILKSCREEN:" at 11488.68,3867.6 h60
  text "X" at 12446.46,3867.6 h60
  text "TOP" at 12563.46,3867.6 h60
  text "X" at 12956.46,3867.6 h60
  text "BOTTOM" at 13074.46,3867.6 h60
  text "SILKSCREEN COLOR:" at 11488.68,3712.41 h60
  text "X" at 12445.46,3712.41 h60
  text "WHITE" at 12563.46,3712.41 h60
  text "OTHER" at 13074.46,3712.41 h60
  text "X" at 12576.46,3568.96 h60
  text "GREEN" at 12694.46,3568.96 h60
  text "OTHER" at 13312.46,3568.96 h60
  text "SOLDER RESIST COLOR:" at 11488.68,3562.1 h60
  text "X" at 12576.46,3414.71 h60
  text "MATTE" at 12694.46,3414.71 h60
  text "SEMI-GLOSS" at 13312,3414.07 h60
  text "IMMERSION GOLD (ENIG)" at 12394.46,3241.94 h60
  text "ENEPIG" at 13732,3234.72 h60
  text "SURFACE FINISH:" at 11333.46,3233.72 h60
  text "X" at 12216.46,3233.72 h60
  text "IMM. TIN/SILVER OR EQUIV" at 11663,3096.4 h60
  text "OTHER" at 13094.46,3092.47 h60
  text "ARRAY/PANEL:" at 11333.46,2937.09 h60
  text "CUT AND TRIM PER M1 BOARD OUTLINE" at 12394.46,2928.87 h60
  text "N.C. ROUTE" at 12394.46,2792.9 h60
  text "X" at 13082.46,2792.9 h60
  text "V. SCORE" at 13260.46,2792.9 h60
  text "CERTIFICATION:" at 11333.46,2663.77 h60
  text "MATERIALS AND WORKMANSHIP FOR ALL PCBS" at 12058.46,2663.77 h60
  text "TO MEET OR EXCEED THE REQUIREMENTS OF:" at 12058.46,2569.71 h60
  text "X" at 11695.97,2441.08 h60
  text "ANSI IPC-A-600F CLASS ->" at 11823.96,2441.08 h60
  text "X" at 13471.97,2441.08 h60
  text "2" at 13581.96,2441.08 h60
  text "1" at 13266.96,2439.58 h60
  text "3" at 13935.96,2439.58 h60
  text "X" at 12507.97,2293.39 h60
  text "RoHS" at 12635.96,2293.39 h60
  text "OTHER" at 13280.36,2293.39 h60
  text "PER ORDER" at 13677.42,2293.39 h60
  text "ALL BOARDS MUST MEET OR EXCEED UL94-V0 REQUIREMENTS." at 11361,2139.57 h60
  text "PCB MUST BEAR THE UL94V-0 UL REGISTERED MATERIAL ID NUMBER" at 11361,2023.5 h60
  text "ADDITIONAL REQUIREMENTS:" at 11333.46,1854.08 h60
  text "MICROSECTION:" at 11408.23,1746.95 h60
  text "YES" at 12313.96,1746.95 h60
  text "REQUIRED" at 13175.46,1602.62 h60
  text "BARE BOARD ELEC. TEST:" at 11408.23,1599.76 h60
  text "NONE" at 12713.96,1599.76 h60
  text "X" at 13057.46,1599.76 h60
  text "PER ORDER" at 13767.46,1599.76 h60
  text "XX MIL VIAS REQUIRE NON-CONDUCTIVE FILL AND PLANARIZE" at 11576.38,1394.82 h59
  text "XX MIL VIAS REQUIRE CONDUCTIVE FILL AND PLANARIZE" at 11584.38,1290.84 h60
  text "OUTER XX MIL TRACES REQUIRE 50 OHM SINGLE-ENDED IMPEDANCE" at 11583.39,1127.46 h58
  text "LAYER 2 & 3 (INNER LAYERS) XX MIL WIDE, XX MIL SPACE / TRACES REQUIRE 100 OHM DIFFERENTIAL IMPEDANCE" at 11575.39,891.74 h60
  text ".Layer_Name" at 577,-858.49 h60
M11 Gerber Information:
  lines w10: -292,-930.17 6308,-930.17 ; -292,-726.83 6310,-726.83 ; -292,-523.5 -292,-1133.5 3713,-1133.5 6310,-1133.5 6310,-523.5 -291.5,-523.5 -291.5,-1133.5 1284,-1133.5 ; 2173,-1133.5 2173,-523.5 ; 3440,-726.83 3440,-523.5 ; 4280,-726.83 4280,-523.5 ; 4902,-1140 4902,-937.17
  text "ALL ARTWORK VIEWED FROM TOP SIDE" at -228.5,-655.67 h60
  text "BOARD #:" at 2248,-655.67 h60
  text ".PRJ_Number" at 2793.5,-655.67 h60
  text "REV:" at 3638,-655.67 h60
  text ".PCB_Rev" at 3929.5,-655.67 h60
  text "SVN REV:" at 4476,-655.67 h60
  text ".VersionControl_RevNumber" at 4982,-655.67 h60
  text "LAYER NAME =" at -228.5,-858.49 h60
  text "TID #:" at 2248,-859 h60
  text ".TID" at 2793.5,-859 h60
  text "PLOT NAME =" at -228.5,-1064.34 h60
  text ".plot_File_Name" at 577,-1064.34 h60
  text "GENERATED    :" at 2250,-1064.34 h60
  text ".Print_Date" at 3119.5,-1064.34 h60
  text ".Print_Time" at 3848.5,-1064.34 h60
  text "TEXAS INSTRUMENTS" at 5113,-1064.34 h60
M12 Stackup:
  drawing of 295 lines, arcs and shapes, not listed
  text "Layer" at 9796.35,7834 h60
  text "Name" at 10206.26,7834 h60
  text "Material" at 11146,7834 h60
  text "Thickness" at 12005.77,7834 h60
  text "Constant" at 12655.6,7834 h60
  text "Board Layer Stack" at 13225.46,7834 h60
  text "1" at 9796.35,7714 h60
  text "Top Overlay" at 10206.26,7714 h60
  text "2" at 9796.35,7594 h60
  text "Top Solder" at 10206.26,7594 h60
  text "Solder Resist" at 11146,7594 h60
  text "0.40mil" at 12005.77,7594 h60
  text "3.5" at 12655.6,7594 h60
  text "3" at 9796.35,7474 h60
  text "Top Layer" at 10206.26,7474 h60
  text "Copper" at 11146,7474 h60
  text "2.80mil" at 12005.77,7474 h60
  text "4" at 9796.35,7354 h60
  text "Dielectric1" at 10206.26,7354 h60
  text "FR-4" at 11146,7354 h60
  text "10.00mil" at 12005.77,7354 h60
  text "4.8" at 12655.6,7354 h60
  text "5" at 9796.35,7234 h60
  text "Signal Layer 1" at 10206.26,7234 h60
  text "Copper" at 11146,7234 h60
  text "2.80mil" at 12005.77,7234 h60
  text "6" at 9796.35,7114 h60
  text "Dielectric 2" at 10206.26,7114 h60
  text "10.00mil" at 12005.77,7114 h60
  text "4.2" at 12655.6,7114 h60
  text "7" at 9796.35,6994 h60
  text "Signal Layer 2" at 10206.26,6994 h60
  text "Copper" at 11146,6994 h60
  text "2.80mil" at 12005.77,6994 h60
  text "8" at 9796.35,6874 h60
  text "Dielectric 3" at 10206.26,6874 h60
  text "10.00mil" at 12005.77,6874 h60
  text "4.2" at 12655.6,6874 h60
  text "9" at 9796.35,6754 h60
  text "Bottom Layer" at 10206.26,6754 h60
  text "Copper" at 11146,6754 h60
  text "2.80mil" at 12005.77,6754 h60
  text "10" at 9796.35,6634 h60
  text "Bottom Solder" at 10206.26,6634 h60
  text "Solder Resist" at 11146,6634 h60
  text "0.40mil" at 12005.77,6634 h60
  text "3.5" at 12655.6,6634 h60
  text "11" at 9796.35,6514 h60
  text "Bottom Overlay" at 10206.26,6514 h60
  text ".Layer_Name" at 577,-858.49 h60
M13 Component Bodies Top:
  text ".Layer_Name" at 577,-858.49 h60
M14 Component Bodies Bottom:
  text ".Layer_Name" at 577,-858.49 h60
M15 Courtyards Top:
  text ".Layer_Name" at 577,-858.49 h60
M16 Courtyards Bottom:
  text ".Layer_Name" at 577,-858.49 h60
Drill Drawing:
  circle w10: c6089.72,2542.96 r16.58
  circle w10: c6089.72,2542.96 r27.63
  circle w10: c6089.72,2045.68 r27.63
  lines w10: 6062.09,1410.27 6075.9,1410.27 6089.72,1396.46 6103.53,1410.27 6117.34,1410.27 6103.53,1424.08 6117.34,1437.9 6103.53,1437.9 6089.72,1451.71 6075.9,1437.9 6062.09,1437.9 6075.9,1424.08 6062.09,1410.27 ; 6062.09,1548.4 6089.72,1520.78 6117.34,1548.4 6089.72,1576.03 6062.09,1548.4 ; 6062.09,1700.35 6117.34,1700.35 6089.72,1645.1 6062.09,1700.35 ; 6062.09,1769.42 6089.72,1783.23 6117.34,1769.42 6103.53,1797.04 6117.34,1824.67 6089.72,1810.86 6062.09,1824.67 6075.9,1797.04 6062.09,1769.42 ; 6062.09,1907.55 6075.9,1907.55 6089.72,1893.74 6103.53,1907.55 6117.34,1907.55 6103.53,1921.36 6117.34,1935.18 6103.53,1935.18 6089.72,1948.99 6075.9,1935.18 6062.09,1935.18 6075.9,1921.36 6062.09,1907.55 ; 6062.09,2156.19 6075.9,2156.19 6075.9,2142.38 6103.53,2142.38 6103.53,2156.19 6117.34,2156.19 6117.34,2183.82 6103.53,2183.82 6103.53,2197.63 6075.9,2197.63 6075.9,2183.82 6062.09,2183.82 6062.09,2156.19 ; 6062.09,2266.7 6117.34,2266.7 6117.34,2321.95 6062.09,2321.95 6062.09,2266.7 ; 6062.09,2391.02 6062.09,2404.83 6075.9,2418.64 6062.09,2432.46 6062.09,2446.27 6075.9,2446.27 6089.72,2432.46 6103.53,2446.27 6117.34,2446.27 6117.34,2432.46 6103.53,2418.64 6117.34,2404.83 6117.34,2391.02 6103.53,2391.02 6089.72,2404.83 6075.9,2391.02 6062.09,2391.02 ; 6062.09,2639.66 6117.34,2639.66 6117.34,2694.91 6062.09,2694.91 6062.09,2639.66 ; 6073.14,1415.79 6081.43,1415.79 6089.72,1407.51 6098.01,1415.79 6106.29,1415.79 6098.01,1424.08 6106.29,1432.37 6098.01,1432.37 6089.72,1440.66 6081.43,1432.37 6073.14,1432.37 6081.43,1424.08 6073.14,1415.79 ; 6073.14,1689.3 6106.29,1689.3 6089.72,1656.15 6073.14,1689.3 ; 6073.14,2650.71 6106.29,2650.71 6106.29,2683.86 6073.14,2683.86 6073.14,2650.71
  lines w12: 6012,1359.16 9243.49,1359.16 ; 6012,2726.68 9243.49,2726.68 ; 6349.86,1234.84 6349.86,2851 ; 6681.86,1234.84 6681.86,2851 ; 7318.43,1234.84 7318.43,2851 ; 7577.57,1234.84 7577.57,2851 ; 7952.72,1234.84 7952.72,2851 ; 8677.05,1234.84 8677.05,2851 ; 6012,1234.84 9243.49,1234.84 9243.49,2851 6012,2851 6012,1234.84
  text "Symbol" at 6086.59,2763.98 h72
  text "Quantity" at 6387.16,2763.98 h72
  text "Finished Hole Size" at 6719.16,2763.98 h72
  text "Plated" at 7355.72,2763.98 h72
  text "Hole Type" at 7614.86,2763.98 h72
  text "Drill Layer Pair" at 7990.02,2763.98 h72
  text "Hole Tolerance" at 8714.35,2763.98 h72
  text "4" at 6387.16,2639.66 h60
  text "7.87mil (0.200mm)" at 6719.16,2639.66 h60
  text "PTH" at 7355.72,2639.66 h60
  text "Round" at 7614.86,2639.66 h60
  text "Top Layer - Bottom Layer" at 7990.02,2639.66 h60
  text "33" at 6387.16,2515.34 h60
  text "10.00mil (0.254mm)" at 6719.16,2515.34 h60
  text "PTH" at 7355.72,2515.34 h60
  text "Round" at 7614.86,2515.34 h60
  text "Top Layer - Bottom Layer" at 7990.02,2515.34 h60
  text "86" at 6387.16,2391.02 h60
  text "16.00mil (0.406mm)" at 6719.16,2391.02 h60
  text "PTH" at 7355.72,2391.02 h60
  text "Round" at 7614.86,2391.02 h60
  text "Top Layer - Bottom Layer" at 7990.02,2391.02 h60
  text "16" at 6387.16,2266.7 h60
  text "40.00mil (1.016mm)" at 6719.16,2266.7 h60
  text "PTH" at 7355.72,2266.7 h60
  text "Round" at 7614.86,2266.7 h60
  text "Top Layer - Bottom Layer" at 7990.02,2266.7 h60
  text "12" at 6387.16,2142.38 h60
  text "43.31mil (1.100mm)" at 6719.16,2142.38 h60
  text "PTH" at 7355.72,2142.38 h60
  text "Round" at 7614.86,2142.38 h60
  text "Top Layer - Bottom Layer" at 7990.02,2142.38 h60
  text "2" at 6387.16,2018.06 h60
  text "50.00mil (1.270mm)" at 6719.16,2018.06 h60
  text "PTH" at 7355.72,2018.06 h60
  text "Round" at 7614.86,2018.06 h60
  text "Top Layer - Bottom Layer" at 7990.02,2018.06 h60
  text "4" at 6387.16,1893.74 h60
  text "51.18mil (1.300mm)" at 6719.16,1893.74 h60
  text "PTH" at 7355.72,1893.74 h60
  text "Round" at 7614.86,1893.74 h60
  text "Top Layer - Bottom Layer" at 7990.02,1893.74 h60
  text "6" at 6387.16,1769.42 h60
  text "62.00mil (1.575mm)" at 6719.16,1769.42 h60
  text "PTH" at 7355.72,1769.42 h60
  text "Round" at 7614.86,1769.42 h60
  text "Top Layer - Bottom Layer" at 7990.02,1769.42 h60
  text "14" at 6387.16,1645.1 h60
  text "62.99mil (1.600mm)" at 6719.16,1645.1 h60
  text "PTH" at 7355.72,1645.1 h60
  text "Round" at 7614.86,1645.1 h60
  text "Top Layer - Bottom Layer" at 7990.02,1645.1 h60
  text "3" at 6387.16,1520.78 h60
  text "105.12mil (2.670mm)" at 6719.16,1520.78 h60
  text "PTH" at 7355.72,1520.78 h60
  text "Round" at 7614.86,1520.78 h60
  text "Top Layer - Bottom Layer" at 7990.02,1520.78 h60
  text "3" at 6387.16,1396.46 h60
  text "160.00mil (4.064mm)" at 6719.16,1396.46 h60
  text "PTH" at 7355.72,1396.46 h60
  text "Round" at 7614.86,1396.46 h60
  text "Top Layer - Bottom Layer" at 7990.02,1396.46 h60
  text "183 Total" at 6387.16,1272.14 h60
  text ".Layer_Name" at 577,-858.49 h60
M17 Embedded Cavity:
  text ".Layer_Name" at 577,-858.49 h60
M18 Embedded Assembly:
  text ".Layer_Name" at 577,-858.49 h60
M19 Embedded Keepout:
  text ".Layer_Name" at 577,-858.49 h60

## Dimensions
0,-400 to 1000,-400 on M2 Board Dimensions
0,0 to 0,3937.01 on M2 Board Dimensions
0,0 to 4330.71,0 on M2 Board Dimensions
